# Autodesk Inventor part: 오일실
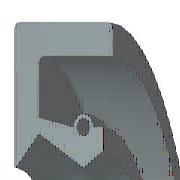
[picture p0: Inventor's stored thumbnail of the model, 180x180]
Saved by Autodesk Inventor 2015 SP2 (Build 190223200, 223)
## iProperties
IsCustomPart: 0
Company: 한국ATC센터
Created: 2014-10
Part Number: 오일실
Material: 고무
Description: 오일-실
Document SubType Name: Modeling
Standard: KS B 2804
Designer: KYOUNG IL JANG
Standards Organization: KS
Language: ko-KR
Size Designation: D - 17 32 8
Categories: <MemberInstance><Categories><Category DisplayName="샤프트 부품" InternalName="7f7aeb1f-a693-4053-b835-cee3144e0d98" Mnemonic="SHFT"><Category DisplayName="실링" Intern
Density: 0.93 g/cm^3
Mass: 2.28027 g
Surface Area: 32.1224 cm^2
Volume: 2.45191 cm^3
Appearance: 고무 - 검은색 - 버전 1.1
Author: KYOUNG IL JANG
Revision Number: 1
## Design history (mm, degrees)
revolve "본체" stored, may be unused: angle "d17" = 90 deg
revolve "스프링1" stored, may be unused: angle "d18" = 90 deg
body "Solid1"
sketch "스케치1"
  geometry: L1 (0, 16)-(8, 16); L2 (8, 14.25)-(1.75, 14.25); L3 (1.75, 10.25)-(4.9, 8.5); L4 (4.9, 8.5)-(0, 8.5); L5 (0, 0)-(9.586, 0) reference; L6 (4.9, 8.5)-(6.3, 9.375); L7 (0, 18)-(0, -3) reference; L8 (-1.941, 0)-(11.507, 0) reference; L9 (4.2, 10.6)-(1.75, 11.21); L10 (1.75, 11.21)-(1.75, 14.25); L11 (0, 16)-(0, 8.588); L12 (4.9, 8.5)-(0, 8.5); L13 (1.75, 10.25)-(0.152, 8.528); L14 (8, 16)-(8, 14.25); L15 (5.6, 10.6)-(6.3, 10.6); L16 (6.3, 10.6)-(6.3, 9.375); C1 r 0.455 at (4.9, 10.6); A1 r 0.7 centre (4.9, 10.6) between (5.6, 10.6) and (4.2, 10.6); A2 r 0.088 centre (0.088, 8.588) between (0, 8.588) and (0.152, 8.528); 1 further point
  constraints: 28 end point, 5 horizontal alignment, 5 point on line, 4 point on circle, 4 vertical alignment, 3 centre point, 3 tangent, 2 collinear, 2 horizontal, 2 perpendicular, 1 coincident, 1 parallel
  dimensions: "d0" = 32 diameter of L1 L5 (= SD2); "d1" = 1.75 distance of L1.end L2.start (= SD); "d2" = 0.91 diameter of C1 (= SPDI); "d3" = 1.4 diameter of A1 (= SPDA); "d4" = 17 diameter of L3.end L5 (= NND); "d5" = 20.5 diameter of L3.start L5 (= TKDM); "d7" = 22.42 diameter of L9.end L5 (= TKDM + 0.24 x SWDT); "d8" = 1.75 distance between parallel lines of L11 L10 (= SD); "d9" = 4.9 distance from line of L11 C1.centre (= SPDST); "d10" = 21.2 diameter of C1.centre L5 (= HLDM); "d11" = 0.0875 radius of A2 (= 0.25 x LAB); "d12" = 6.3 distance between parallel lines of L11 L16 (= SDI); "d13" = 18.75 diameter of L6.end L5 (= ABDM); "d14" = 8 distance from line of L11 L1.end (= SWDT)
fillet "모깎기1" dims "d6" = 0.3 (= RR)
other parameters: "SD2" = 32 [user parameter; used in 1 equation term], "SWDT" = 8 [user parameter; used in 2 equation terms], "RR" = 0.3 [user parameter; used in 1 equation term], "SD" = 1.75 [user parameter; used in 2 equation terms], "NND" = 17 [user parameter; used in 1 equation term], "SPDA" = 1.4 [user parameter; used in 1 equation term], "SPDI" = 0.91 [user parameter; used in 1 equation term], "TKDM" = 20.5 [user parameter; used in 2 equation terms], "HLDM" = 21.2 [user parameter; used in 1 equation term], "ABDM" = 18.75 [user parameter; used in 1 equation term], "SDI" = 6.3 [user parameter; used in 1 equation term], "SPDST" = 4.9 [user parameter; used in 1 equation term], "LAB" = 0.35 [user parameter; used in 1 equation term], "d15" = 0, "d16" = 0, "d19" = 0
